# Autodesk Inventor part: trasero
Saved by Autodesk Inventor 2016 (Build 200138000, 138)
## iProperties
Created: 2013-03
Part Number: trasero
Material: Generic
Document SubType Name: Modeling
Designer: julian.chica
Density: 1 g/cm^3
Appearance: Default
Author: julian.chica
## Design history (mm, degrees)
derived "Parlante_INICIAL.ipt"
feature "trasero::Parlante_INICIAL.ipt" dims "d0" = 10
tag "TaggingFeature1"
body "Solid1"
